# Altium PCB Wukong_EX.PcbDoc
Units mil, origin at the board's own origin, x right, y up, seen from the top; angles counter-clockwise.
Board outline 2015.75 x 1811.02 mil, 4 copper layers (Top Layer, Internal Plane 1, MidLayer2, Bottom Layer), stack 33.217 mil thick; 59 components, 65 nets, 213 pads, 28 vias.
Unrouted connection lines stored in the file: 1.
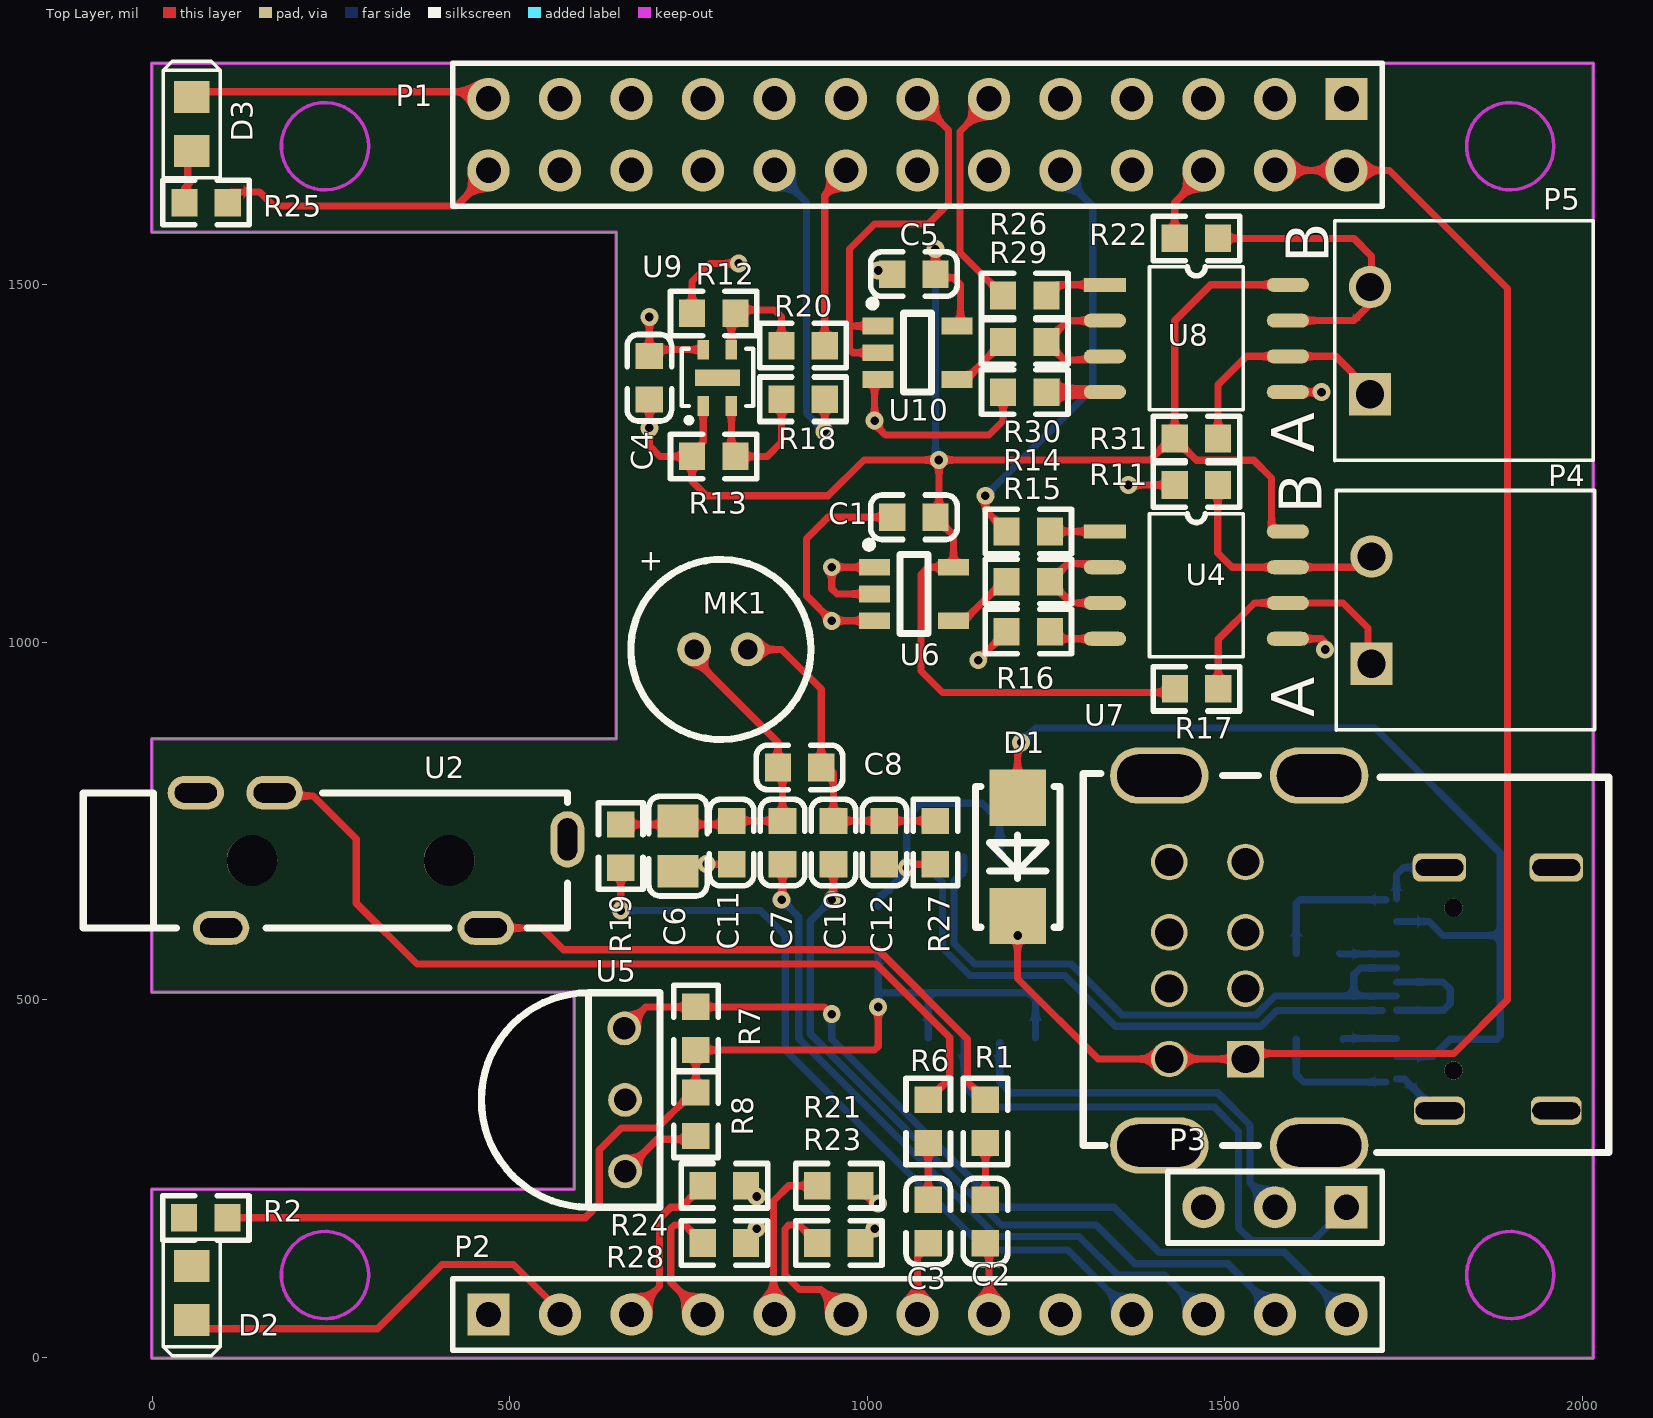
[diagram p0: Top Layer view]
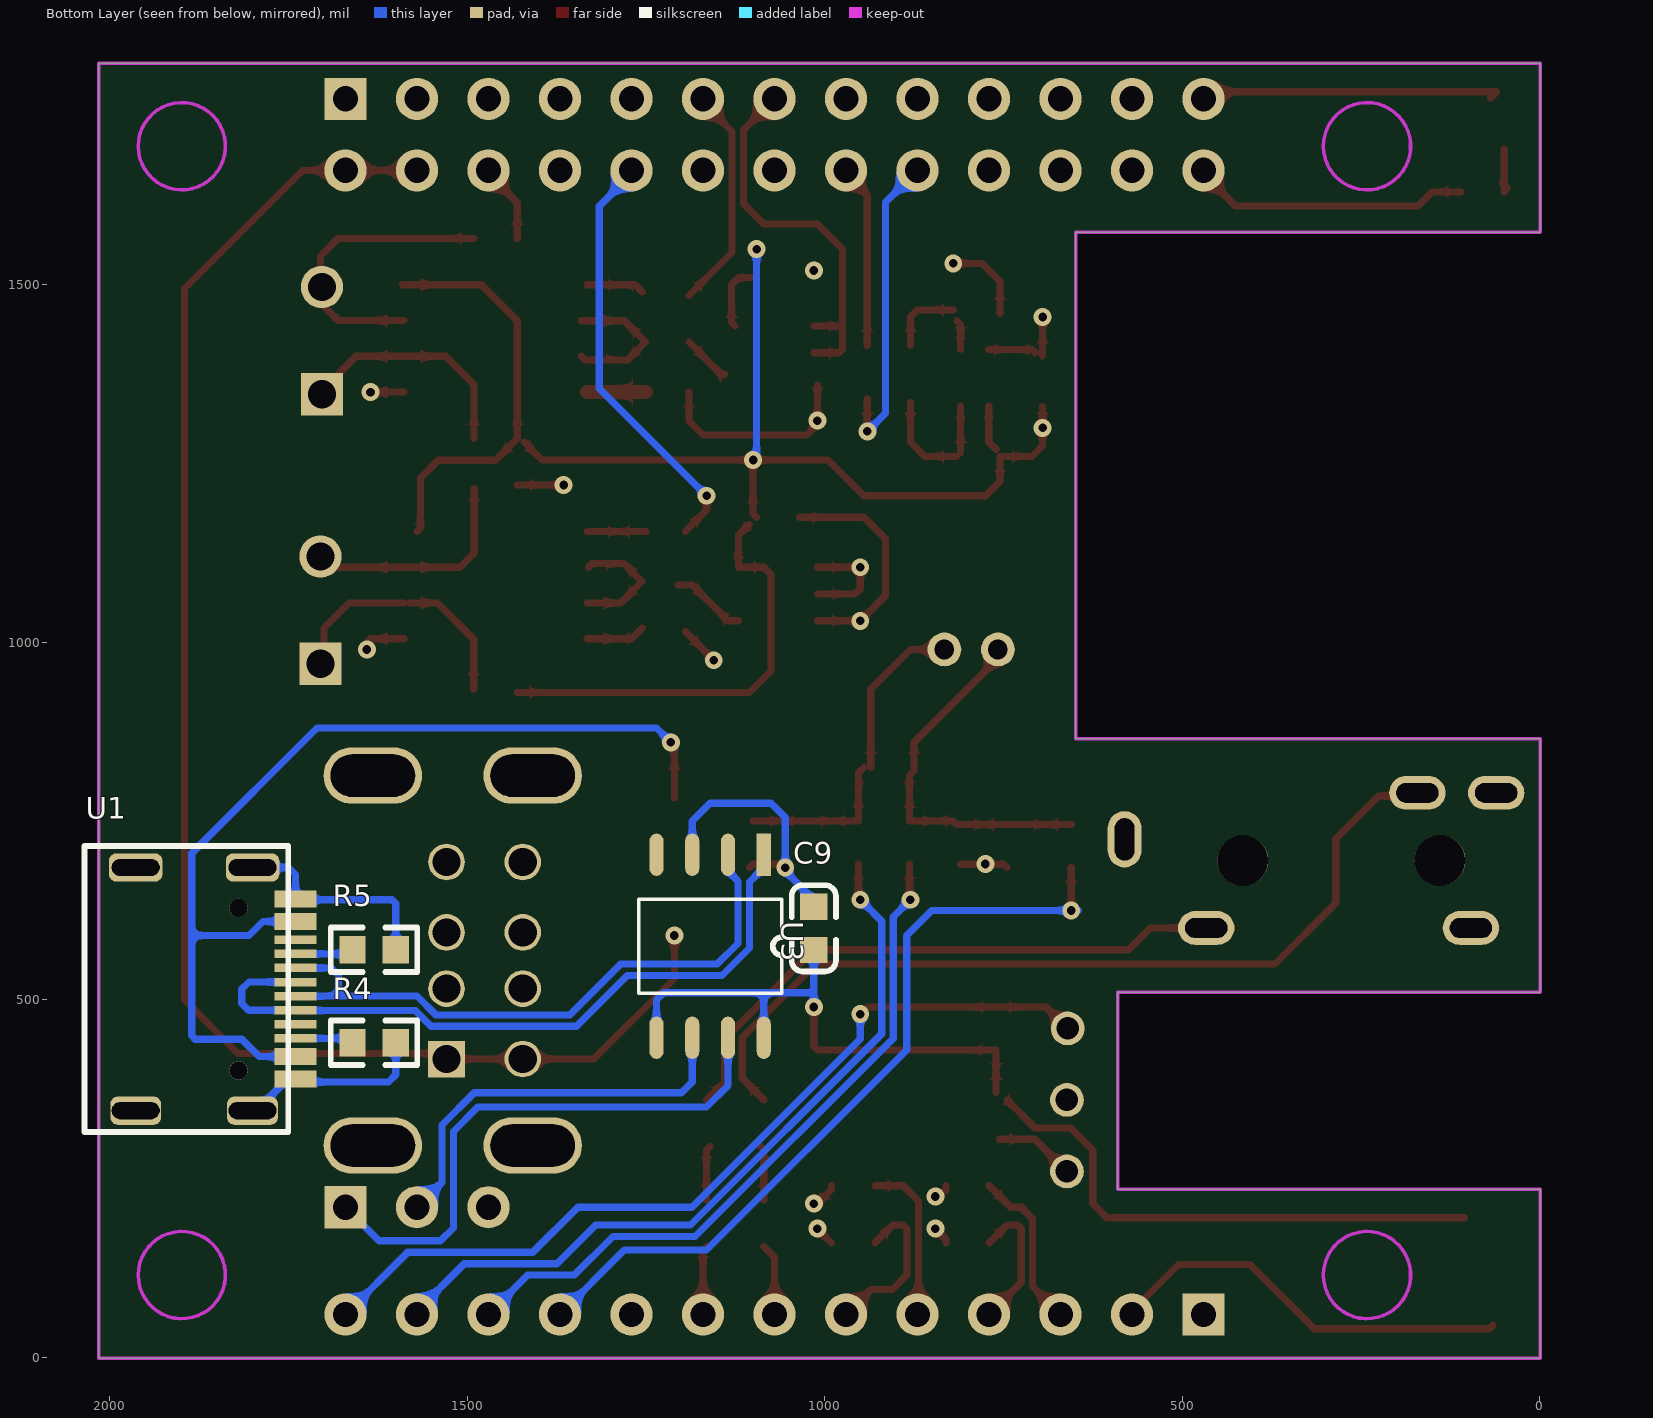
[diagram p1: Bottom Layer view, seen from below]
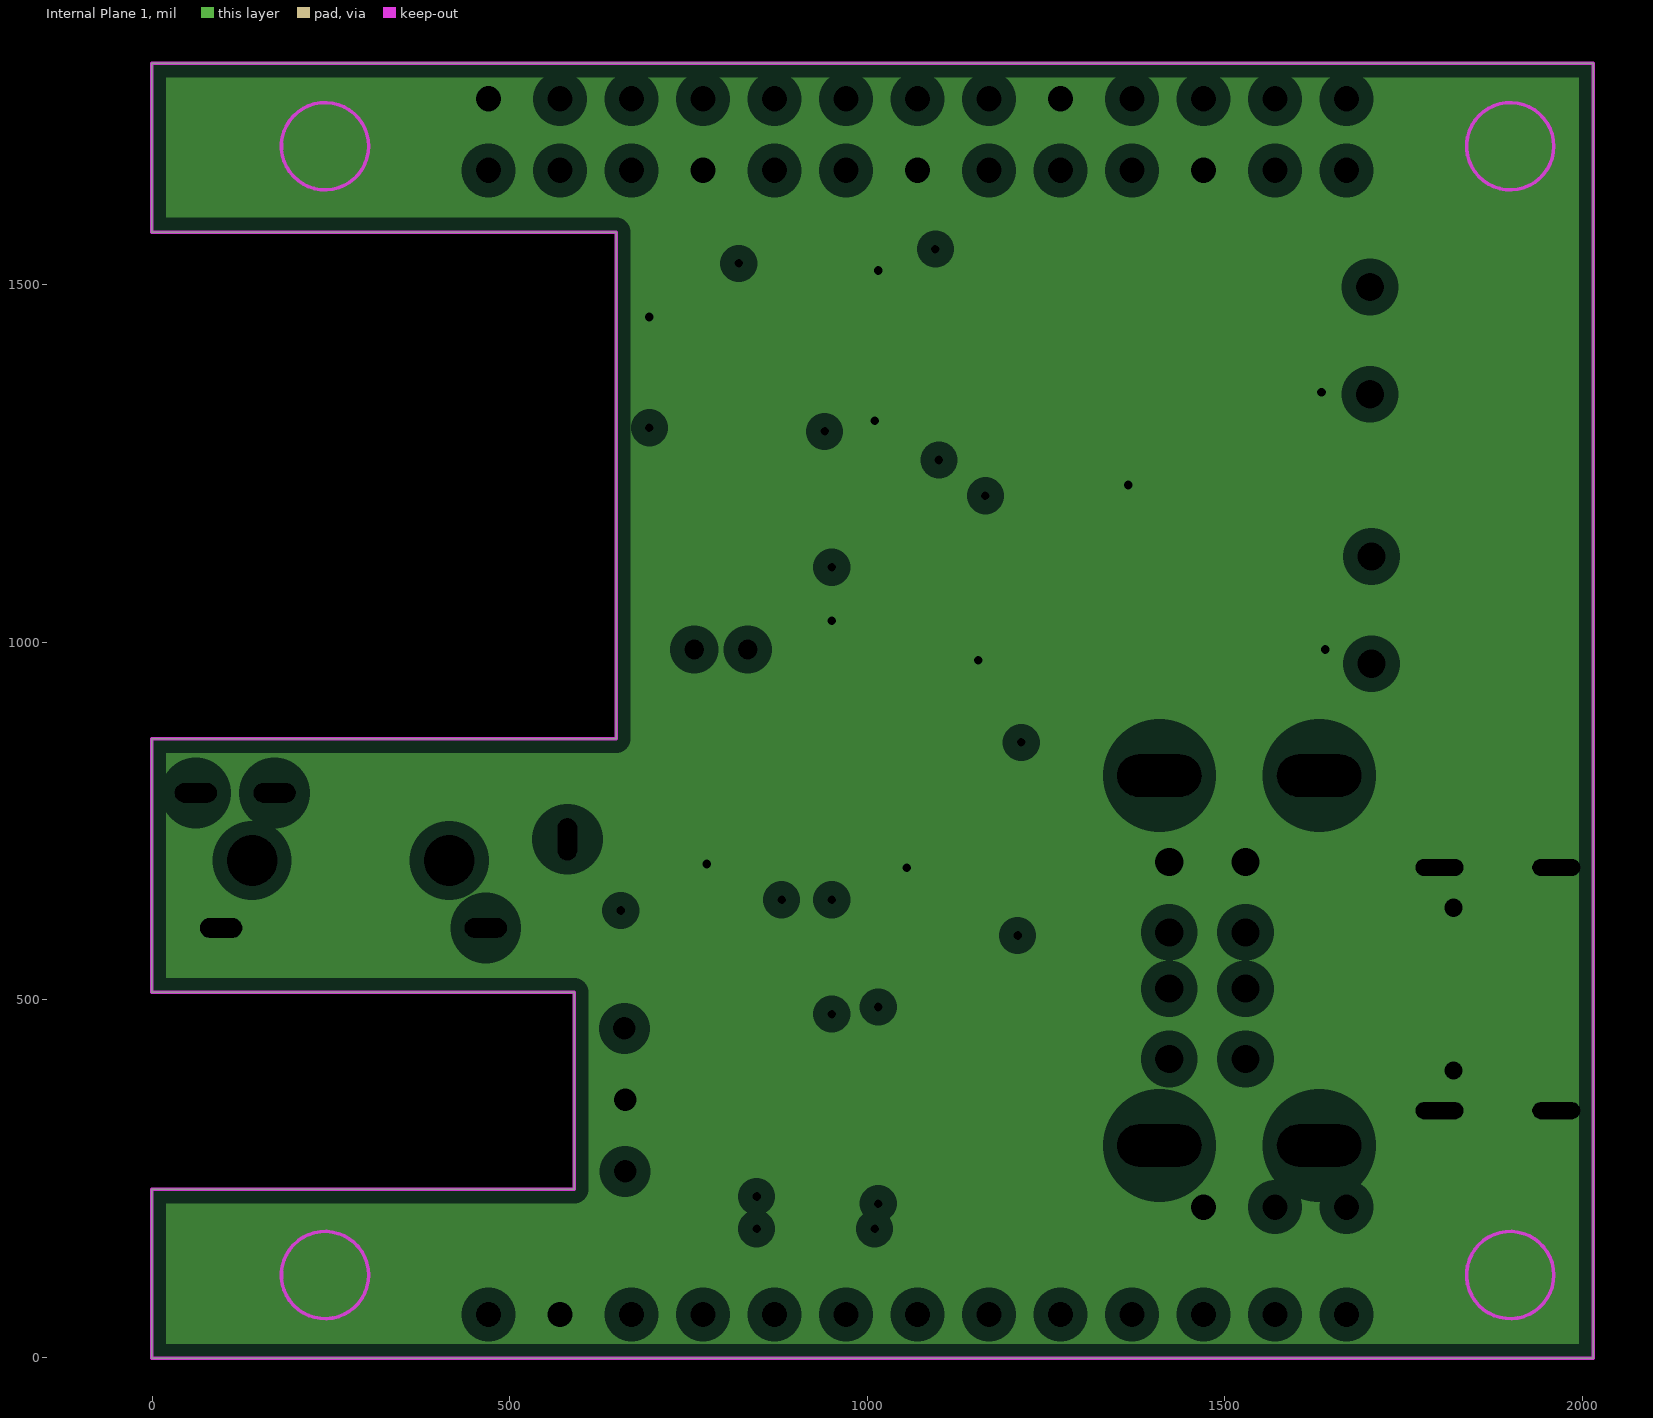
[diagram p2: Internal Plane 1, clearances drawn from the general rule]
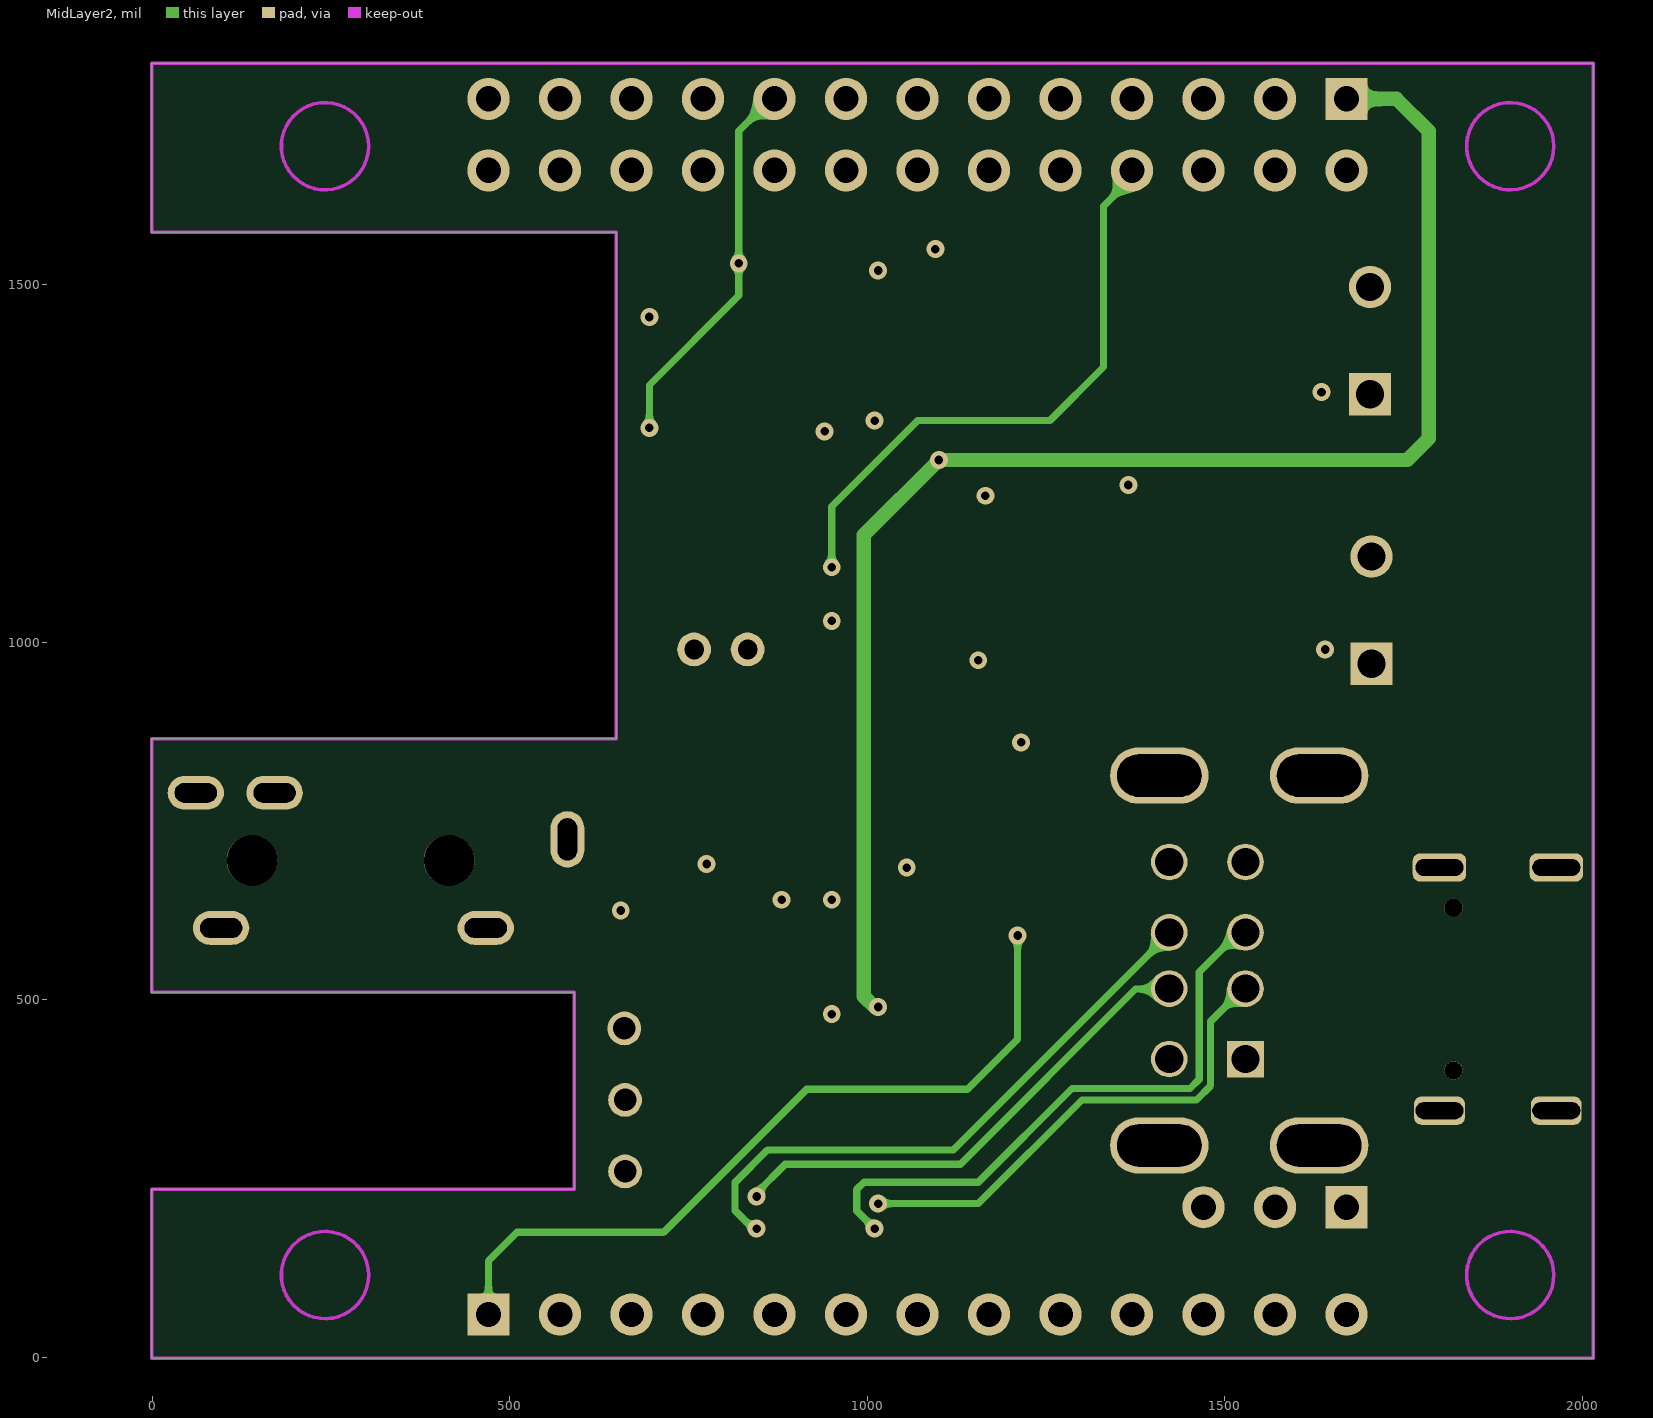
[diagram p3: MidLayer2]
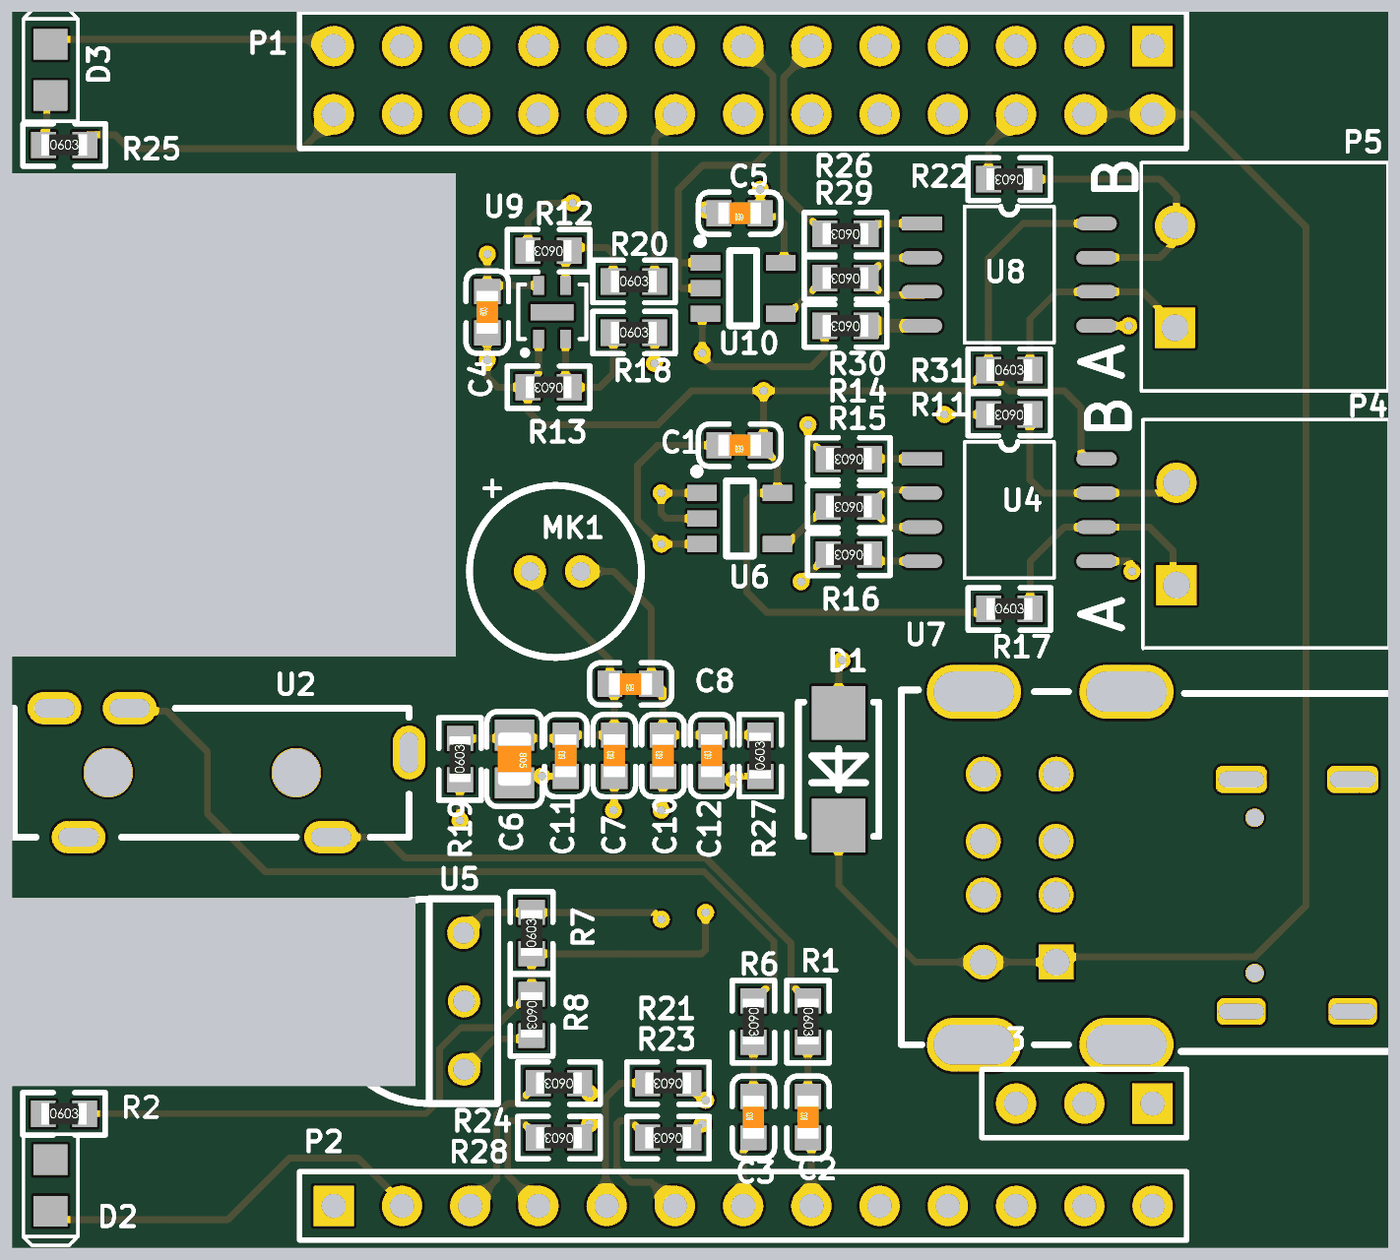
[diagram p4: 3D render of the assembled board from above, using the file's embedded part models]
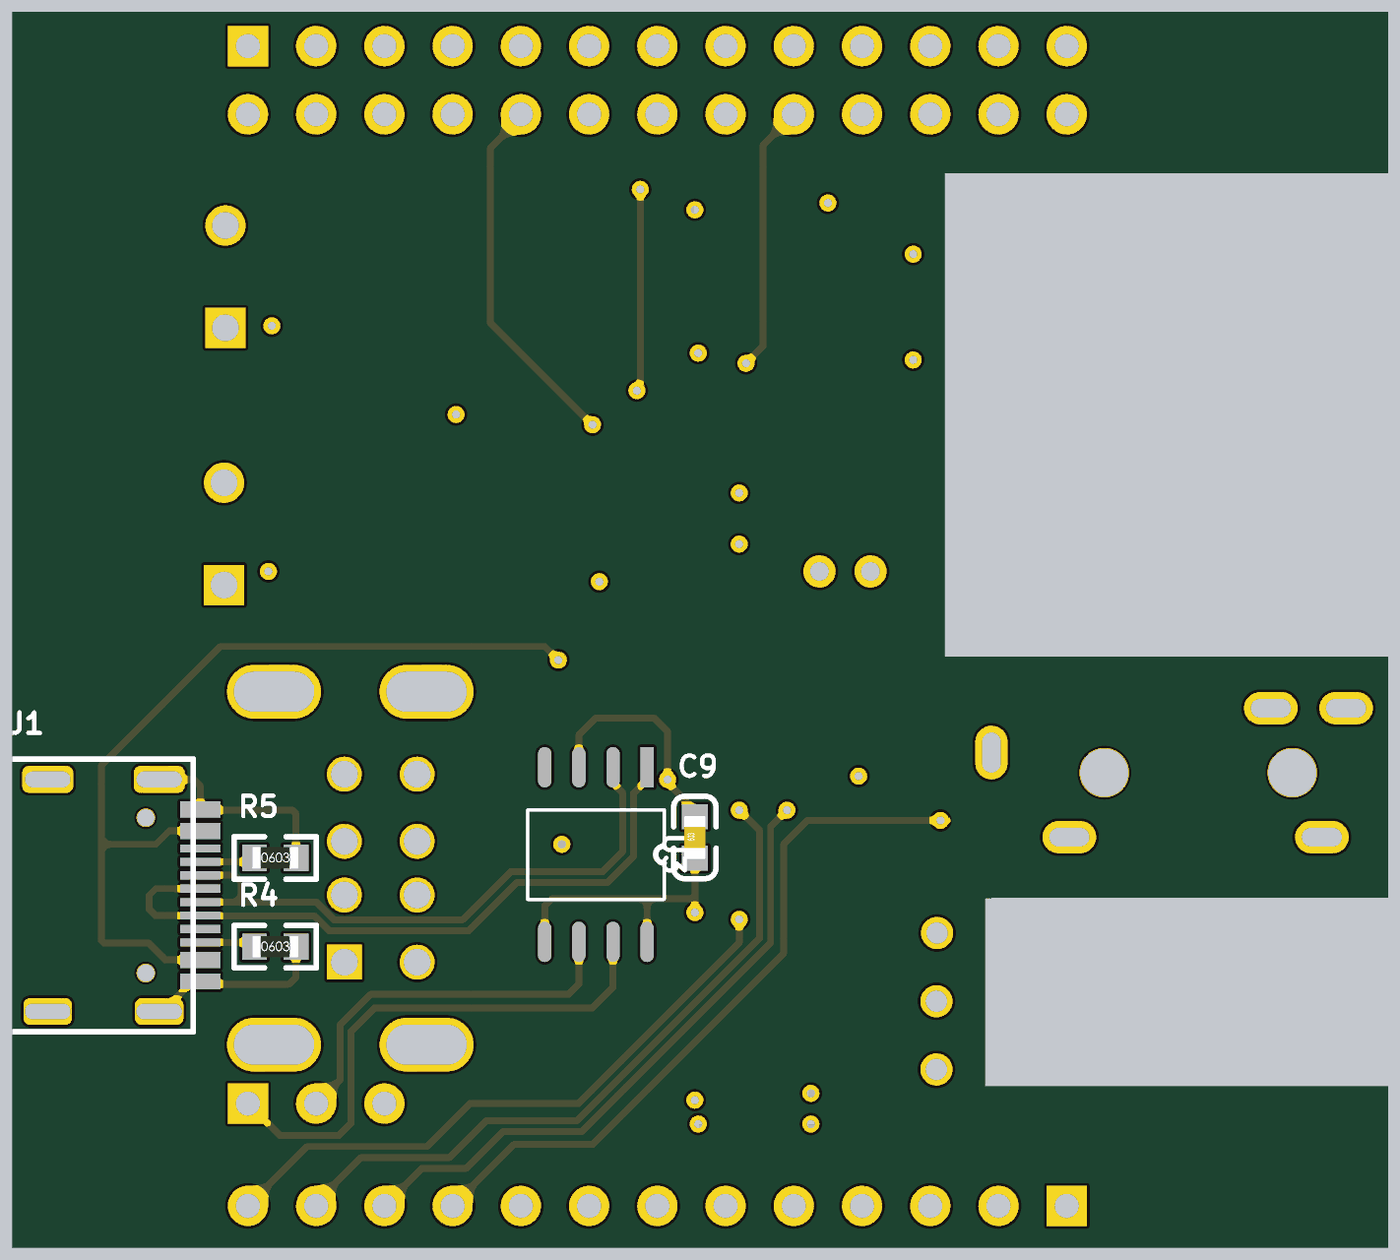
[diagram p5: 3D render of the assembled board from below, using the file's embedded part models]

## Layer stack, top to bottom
Top Solder: solder mask 0.4, Solder Resist, Dk 3.5
Top Layer: signal copper 1.4
Dielectric1: core 12.6, FR-4, Dk 4.8
Internal Plane 1: plane copper 1.417, net GND
Dielectric3: core 10, FR-4, Dk 4.2
MidLayer2: signal copper 1.4
Dielectric 4: prepreg 5, Dk 4.2
Bottom Layer: signal copper 1.4
Bottom Solder: solder mask 0.4, Solder Resist, Dk 3.5

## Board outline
-0.75,-1.01 -0.75,235.21 589.8,235.21 589.8,510.8 -0.75,510.8 -0.75,865.13 648.86,865.13 648.86,1573.79 -0.75,1573.79 -0.75,1810.01 2015,1810.01 2015,-1.01

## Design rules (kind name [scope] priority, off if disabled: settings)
Clearance [All] p1: gap=6
FabricationTestPointUsage TestPointUsage [All] p1: valid=0 allowmultiple=FALSE
FabricationTestpoint Testpoint [All] p1: side=3 testpointundercomponent=TRUE minsize=40 maxsize=100 preferedsize=60 minholesize=0 maxholesize=40 preferedholesize=32 testpointgrid=1 allowsidetop=TRUE allowsidebottom=TRUE usegrid=TRUE gridtolerance=0.01
PlaneClearance [All] p1: clearance=20
PlaneConnect [All] p1: planeconnectstyle=Relief reliefexpansion=20 reliefentries=4 reliefconductorwidth=10 reliefairgap=10
PolygonConnect [All] p1: connectstyle=Relief reliefconductorwidth=10 reliefentries=4 polygonreliefangle="90 Angle" airgapwidth=10
RoutingVias [All] p1: holewidth=28 width=50 viastyle="Through Hole" minholewidth=28 minwidth=50 maxholewidth=28 maxwidth=50
SilkToSolderMaskClearance SilkscreenOverComponentPads [IsPad] p1: minsilkscreentomaskgap=10 clearancetoexposedcopper=TRUE
SolderMaskExpansion [All] p1: expansion=4
Width [All] p1: maxlimit=50 minlimit=10 preferedwidth=10
25 further rules are at their usual default settings.

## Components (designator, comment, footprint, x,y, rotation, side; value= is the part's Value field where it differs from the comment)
C1 "CAP" C0603 1065,1175 r180 top
C2 "CAP" C0603 1165,190 r90 top
C3 "CAP" C0603 1085,190 r90 top
C4 "CAP" C0603 695,1370 r90 top
C5 "CAP" C0603 1065,1515 r180 top
C6 "CAP" C0805 735,715 r270 top
C7 "CAP" C0603 881.25,720 r90 top
C8 "CAP" C0603 905,825 r180 top
C9 "CAP" C0603 1015,600 r90 bottom
C10 "CAP" C0603 952.5,720 r90 top
C11 "CAP" C0603 810,720 r90 top
C12 "CAP" C0603 1023.75,720 r90 top
D1 "1N4007" DO-214AC 1210,700 r90 top
D2 "LED" LED_0805 55,90 r270 top
D3 "LED" LED_0805 55,1725 r90 top
MK1 "MIC" MIC 795,990 r0 top
P1 "Header 13X2" HDR2X13 1670,1760 r180 top locked
P2 "Header 13" HDR1X13 470,60 r0 top locked
P3 "Header 3" HDR1X3 1670,210 r180 top locked
P4 "WJ15EDGRC-3.81-2P6GR" WJ15EDGRC-3.81-2P6GR 2017.02,878 r90 top
P5 "WJ15EDGRC-3.81-2P6GR" WJ15EDGRC-3.81-2P6GR 2015,1255 r90 top
R1 "RES" R0603 1165,330 r270 top
R2 "RES" R0603 74.68,195 r0 top
R4 "RES" R0603 1630,440 r180 bottom
R5 "RES" R0603 1630,570 r180 bottom
R6 "RES" R0603 1085,330 r270 top
R7 "RES" R0603 760,460 r90 top
R8 "RES" R0603 760,340 r270 top
R11 "RES" R0603 1460,1220 r180 top
R12 "RES" R0603 785,1460 r180 top
R13 "RES" R0603 785,1260 r180 top
R14 "RES" R0603 1225,1155 r180 top
R15 "RES" R0603 1225,1085 r180 top
R16 "RES" R0603 1225,1015 r180 top
R17 "RES" R0603 1460.31,935 r0 top
R18 "RES" R0603 910,1340 r0 top
R19 "RES" R0603 655,715 r90 top
R20 "RES" R0603 910,1415 r0 top
R21 "RES" R0603 960,240 r180 top
R22 "RES" R0603 1460,1565 r180 top
R23 "RES" R0603 960,160 r180 top
R24 "RES" R0603 800,240 r180 top
R25 "RES" R0603 75,1615 r0 top
R26 "RES" R0603 1220,1485 r180 top
R27 "RES" R0603 1095,720 r90 top
R28 "RES" R0603 800,160 r180 top
R29 "RES" R0603 1220,1420 r180 top
R30 "RES" R0603 1220,1350 r180 top
R31 "RES" R0603 1460,1285 r0 top
U1 "USB-TypeC-16Pin" USB-TYPE-C-16PIN 2035,515 r180 bottom
U2 "PJ328A" PJ-328A -96.81,600.51 r0 top
U3 "CH330" SOIC-8 1160,575 r270 bottom
U4 "Max485" SOIC-8 1460,1080 r0 top
U5 "IRM-3638L" IRM-3638L 660,460 r270 top
U6 "SN74AHCT1G00" SOT-235 1065.12,1067.6 r0 top
U7 "USB_2_UP_W" USB_2_UP_W 2035,555 r90 top locked
U8 "Max485" SOIC-8 1460,1425 r0 top
U9 "SHT-C3" SHTC3 770.32,1330.63 r90 top
U10 "SN74AHCT1G00" SOT-235 1070,1405 r0 top

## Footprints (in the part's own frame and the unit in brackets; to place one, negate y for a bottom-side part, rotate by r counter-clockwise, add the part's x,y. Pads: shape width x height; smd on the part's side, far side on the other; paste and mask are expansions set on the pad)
C0603 [mm]
  rect 0.93x0.98 smd: 1(-0.77,0) 2(0.77,0)
  silkscreen extent -1.53,-0.79 1.54,0.79, body extent -0.8,-0.4 0.8,0.4, height 0.3
C0805 [mm]
  rect 1.16x1.47 smd: 1(-0.89,0) 2(0.89,0)
  silkscreen extent -1.77,-1.04 1.77,1.04, body extent -1,-0.62 1,0.63, height 0.77
DO-214AC [mm]
  rect 2x2 smd: 1(2.1,0) 2(-2.1,0)
  silkscreen extent -2.5,-1.5 2.5,1.5, body extent -3,-1.4 3,1.4, height 2.5
HDR1X3 [mm] "Connector; Header; 3 Position"
  rect 1.5x1.5 hole 0.9: 1(0,0)
  round 1.5 hole 0.9: 2(2.54,0) 3(5.08,0)
  silkscreen extent -1.27,-1.27 6.35,1.27
HDR1X13 [mm] "Connector; Header; 13 Position"
  rect 1.5x1.5 hole 0.9: 1(0,0)
  round 1.5 hole 0.9: 2(2.54,0) 3(5.08,0) 4(7.62,0) 5(10.16,0) 6(12.7,0) 7(15.24,0) 8(17.78,0) 9(20.32,0) 10(22.86,0) 11(25.4,0) 12(27.94,0) 13(30.48,0)
  silkscreen extent -1.27,-1.27 31.75,1.27
HDR2X13 [mm] "Connector; Header; 13x2 Position"
  rect 1.5x1.5 hole 0.9: 1(0,0)
  round 1.5 hole 0.9: 2(0,2.54) 3(2.54,0) 4(2.54,2.54) 5(5.08,0) 6(5.08,2.54) 7(7.62,0) 8(7.62,2.54) 9(10.16,0) 10(10.16,2.54) 11(12.7,0) 12(12.7,2.54) 13(15.24,0) 14(15.24,2.54) 15(17.78,0) 16(17.78,2.54) 17(20.32,0) 18(20.32,2.54) 19(22.86,0) 20(22.86,2.54) 21(25.4,0) 22(25.4,2.54) 23(27.94,0) 24(27.94,2.54) 25(30.48,0) 26(30.48,2.54)
  silkscreen extent -1.27,-1.27 31.75,3.81
IRM-3638L [mm]
  round 1.2 hole 0.8: 1(0,0) 2(2.54,0.025) 3(5.08,0.025)
  silkscreen extent -1.27,-5.08 6.35,1.27, body extent -1.46,-6.28 6.54,1.71, height 8.25
LED_0805 [mm]
  rect 1.14x1.27 smd: 1(-0.955,0) 2(0.955,0)
  silkscreen extent -1.91,-1.02 2.23,1.02, body extent -1,-0.6 1,0.6, height 0.5
MIC [mm]
  round 1.2 hole 0.7: 1(-0.95,0) 2(0.95,0)
  silkscreen extent -3.2,-3.2 3.2,3.2
PJ-328A [mm] "3.5mm耳机接口"
  round 1.8 hole 1.8: 0(6,2.4) 0(13,2.4)
  oval 2x1.2 hole 0.7 slot 1.5 at 0 deg: 3(4.9,0) 4(6.8,4.8) 6(14.3,0) 7(4,4.8)
  oval 1.2x2 hole 0.7 slot 1.5 at 90 deg: 5(17.2,3.15)
  silkscreen extent 0,0 17.2,4.8, body extent 0.04,0 17.23,4.88, height 6
R0603 [mm]
  rect 0.93x0.98 smd: 1(-0.77,0) 2(0.77,0)
  silkscreen extent -1.53,-0.79 1.54,0.79, body extent -0.85,-0.4 0.85,0.4, height 0.56
SHTC3 [mm]
  rect 0.6x1.6 smd: 0(1,-0.5)
  rect 0.7x0.4 smd: 1(0,0) 2(0,-1) 3(2,-1) 4(2,0)
  silkscreen extent -0.57,-1.78 2.03,0.76, body extent 0,-1.78 2.03,0.76, height 0.75
SOIC-8 [mm]
  rect 1.5x0.5 smd: 1(-3.25,1.905)
  oval 1.5x0.5 smd: 2(-3.25,0.635) 3(-3.25,-0.635) 4(-3.25,-1.905) 5(3.25,-1.905) 6(3.25,-0.635) 7(3.25,0.635) 8(3.25,1.905)
  silkscreen extent -1.67,-2.54 1.67,2.54, body extent -1.7,-2.54 1.68,2.57, height 1
SOT-235 [mm]
  rect 1.1x0.6 smd: 1(-1.4,0.95) 2(-1.4,0) 3(-1.4,-0.95) 4(1.4,-0.95) 5(1.4,0.95)
  silkscreen extent -1.72,-1.4 0.5,1.87, body extent -0.89,-1.55 0.89,1.55, height 2
USB-TYPE-C-16PIN [mm]
  rrect50% 1.8x1 hole 0.6 slot 1.7 at 0 deg: 0(1.819,-4.318) 0(5.969,-4.318)
  rrect50% 1.9x1 hole 0.6 slot 1.7 at 0 deg: 0(1.819,4.322) 0(5.969,4.322)
  round 0.65 hole 0.65: 0(5.469,-2.888) 0(5.469,2.892)
  rect 1.5x0.6 smd: 1(7.498,3.202) 2(7.498,2.402) 11(7.498,-2.398) 12(7.498,-3.198)
  rect 1.5x0.3 smd: 3(7.498,1.752) 4(7.498,1.252) 5(7.498,0.752) 6(7.498,0.252) 7(7.498,-0.248) 8(7.498,-0.748) 9(7.498,-1.248) 10(7.498,-1.748)
  silkscreen extent 0,-5.08 7.24,5.08, body extent 0,-5.08 7.24,5.08, height 3
USB_2_UP_W [mm] "双层USB接口,上接触式，90度弯"
  oval 2x3.5 hole 1.5 slot 3 at 90 deg: 0(-6.57,15.921) 0(-6.57,10.241) 0(6.57,15.921) 0(6.57,10.241)
  rect 1.3x1.3 hole 1: 1(-3.5,12.861)
  round 1.3 hole 1: 2(-1,12.861) 3(1,12.861) 4(3.5,12.861) 5(-3.5,15.571) 6(-1,15.571) 7(1,15.571) 8(3.5,15.571)
  silkscreen extent -6.82,-0.05 6.64,18.62, body extent -6.82,-0.05 6.64,18.62, height 15
WJ15EDGRC-3.81-2P6GR [mm]
  rect 1.5x1.5 hole 1: 1(2.337,7.925)
  round 1.5 hole 1: 2(6.147,7.925)
  silkscreen extent -0.03,0 8.49,9.18, body extent 0,-0.05 8.51,9.22, height 7

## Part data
C1 C2 C3 C4 C5 C6 C7 C8 C9 C10 C11 C12: library part 无极电容, "无极电容"
D1: library part 二极管, "二极管"
MK1: "咪头，驻极体话筒"
P1: "Header, 13-Pin, Dual row"
P2: "Header, 13-Pin"
P3: "Header, 3-Pin"
P4 P5: "3.81-2P-Green-90"
R1 R2 R4 R5 R6 R7 R8 R11 R12 R13 R14 R15 R16 R17 R18 R19 R20 R21 R22 R23 R24 R25 R26 R27 R28 R29 R30 R31: "电阻"
U2: library part PJ-328A, "3.5mm音频接口"
U3: "USB 转串口"
U4 U8: "MAX-485"
U5: "红外接收头，38KHz,2.7-5.5V"
U6 U10: "双输入与非门"
U7: library part USB*2, "双层USB接口，上接触式，90度弯"
U9: "温湿度传感器"

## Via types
v1: diameter 25, hole 12, Top Layer to Bottom Layer, 28 vias

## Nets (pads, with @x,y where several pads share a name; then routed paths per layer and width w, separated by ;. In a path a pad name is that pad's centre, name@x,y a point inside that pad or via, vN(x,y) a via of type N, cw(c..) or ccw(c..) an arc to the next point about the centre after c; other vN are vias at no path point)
DP_M: U1.5 U1.7 U3.2 | length 891.6
  Bottom Layer w10: U3.2@1135,700 1135,680 1121,666 1121,579 1150,550 1285,550 1355.96,479.04 1543.82,479.04 1570.01,505.24 1680,505.24 ; 1680,505 1680,505.24 ; U1.7 1680,505.24 ; U1.5 1689.61,544.61 1680,535 1680,505.24
DP_P: U1.6 U1.8 U3.1 | length 986.5
  Bottom Layer w10: U3.1 1085,685 1105,665 1105,572.37 1143.37,534 1276,534 1346.96,463.04 1550.45,463.04 1572.41,485 U1.8@1720,485 ; U1.8 1805.55,485.55 1815,495 1815,515 1805,525 U1.6@1740,525
GND: C1.2 C4.2 C5.2 C6.2 C9.2 C11.1 C12.1 D2.2 D3.2 P1.6 P1.9 P1.14 P1.20 P1.25 P2.2 P3.3 R4.2 R5.2 R11.2 R16.2 R22.2 R27.1 R30.2 U1.0 U1.1 U1.12 U2.3 U3.3 U4.5 U5.2 U6.3 U7.4 U7.8 U8.5 U9.4 U10.3 | length 3075.3
  Top Layer w10: D2.2@65,45 70.04,39.96 314.96,39.96 405,130 505,130 P2.2@575,60 ; D3.2@68.4,1761.63 60.03,1770 455,1770 P1.25@465,1760 ; C4.2 v1(695,1455) ; C4.2@705,1405 709.37,1409.37 U9.4 ; C6.2@745,685 749.69,689.69 C11.1 ; v1(950,1030) 915,1065 915,1145 945,1175 C1.2 ; v1@955,1030 955.2,1030.2 U6.3 ; U10.3@1010,1360 v1(1010,1310) 1010,1305 1025,1290 1170,1290 1189.68,1309.68 R30.2 ; v1@1055,689.69 1100.31,689.69 R27.1@1105,685 ; v1@1155,970 v1(1155,975) 1155,975.32 R16.2 ; v1(1365,1220) R11.2 ; R22.2 1429.68,1614.68 P1.6@1470,1655 ; U4.5 1635,1005 1640,1000 v1(1640,990) ; U8.5 v1(1635,1350)
  Bottom Layer w10: C9.2 1015,640 1055,680 v1(1055,685) 1055,755 1075,775 1160,775 1185,750 U3.3 ; R4.2@1599.68,445 R4.2 1599.68,395.32 1610,385 U1.12@1725,385 ; R5.2@1599.68,565 R5.2 1599.68,634.68 1605,640 U1.1@1725,640 ; U1.12 1750.91,389.09 1795,345 1800,345 U1.0@1805,345 ; U1.1 1739.8,675.2 1749.61,685 U1.0@1790,685
  other v1: 775,690 1015,1520
IR_RX: P2.13 R7.2 U5.1 | length 1220.9
  Top Layer w10: U5.1 690,490 940,490 v1(950,480)
  Bottom Layer w10: v1(950,480) 950,445.25 1185.25,210 1345,210 1408,147 1583,147 P2.13
LINE_OUTL: C2.1 P2.8 | length 97.1
  Top Layer w10: C2.1@1165,155 1170,150 P2.8
LINE_OUTR: C3.1 P2.7 | length 101.2
  Top Layer w10: P2.7 1070,140 C3.1@1085,155
MIC_1N: C10.1 P2.12 | length 1059
  Top Layer w10: C10.1 952.5,642.5 v1@955,640
  Bottom Layer w10: v1@945,635 920,610 920,452.63 1187.63,185 1320,185 1374,131 1504,131 1570,65 P2.12
  other v1: 950,640
MIC_1P: C7.1 P2.11 | length 985
  Top Layer w10: v1(880,640) 881.25,641.25 C7.1
  Bottom Layer w10: v1@880,645 v1(880,640) 904,616 904,446 1181,169 1296,169 1350,115 1415,115 P2.11
MIC_MBIAS: P2.10 R19.1 | length 1114.5
  Top Layer w10: R19.1 655,630 v1@660,625
  Bottom Layer w10: v1@645,625 v1(655,625) 850,625 885,590 885,430 1165,150 1280,150 P2.10
NetC2_2: C2.2 R1.2 | length 76.8
  Top Layer w10: R1.2@1160,295 1165,290 C2.2
NetC3_2: C3.2 R6.2 | length 76.8
  Top Layer w10: C3.2 1085,290 R6.2@1090,295
NetC6_1: C6.1 C7.2 C8.2 C11.2 MK1.1 R19.2 | length 513.4
  Top Layer w10: R19.2 814.68,745.32 815,745 820.32,750.32 C7.2 881.25,813.75 C8.2@875,820 ; MK1.1@760,990 760,975 874.68,860.32 C8.2
NetC8_1: C8.1 C10.2 C12.2 MK1.2 R27.2 | length 463.3
  Top Layer w10: MK1.2@830,990 MK1.2 880,990 935.31,934.69 C8.1 ; C8.1@945,825 952.5,817.5 C10.2 C12.2 1099.68,750.32 R27.2@1100,750
NetD1_1: D1.1 U1.2 U1.11 | length 1405.8
  Top Layer w10: D1.1 1210,860 v1@1215,865
  Bottom Layer w10: v1@1220,860 v1(1215,860) 1235,880 1710,880 1885,705 1885,590 ; U1.11 1790.59,420.59 1815,445 1880,445 1885,450 1885,590 ; U1.2 1785.43,609.57 1805,590 1885,590
NetD2_1: D2.1 R2.1
NetD3_1: D3.1 R25.1 | length 70.7
  Top Layer w10: 45,1635 49.37,1639.37 ; R25.1@49.37,1630 49.37,1639.37 ; D3.1@50,1690 49.37,1689.37 49.37,1639.37 ; 52.4,1642.4 49.37,1639.37
NetR1_1: R1.1 U2.6 | length 833.3
  Top Layer w10: U2.6 544.49,600.51 575,570 1015,570 1140,445 1140,385.31 R1.1
NetR4_1: R4.1 U1.10 | length 75.3
  Bottom Layer w10: R4.1@1665,445 1666.18,446.18 U1.10
NetR5_1: R5.1 U1.4 | length 80.1
  Bottom Layer w10: R5.1@1660,565 1660.71,564.29 U1.4
NetR6_1: R6.1 U2.4 | length 1237.1
  Top Layer w10: U2.4@170,785 225,785 285,725 285,635 370,550 1012.37,550 1115,447.37 1115,390.31 R6.1
NetR8_2: R8.2 U5.3 | length 112.6
  Top Layer w10: U5.3 706,305 R8.2@755,305
NetR12_1: R12.1 R20.1 U9.3 | length 146.8
  Top Layer w10: U9.3 809.69,1444.69 R12.1@815,1450 ; R12.1@820,1465 870,1465 879.69,1455.31 R20.1
NetR13_1: R13.1 R18.1 U9.2 | length 193.7
  Top Layer w10: U9.2 809.69,1265.31 R13.1@810,1265 ; R13.1 860,1260 880,1280 R18.1@880,1335
NetR14_1: R14.1 U4.1 | length 82
  Top Layer w10: R14.1@1250,1155 R14.1 U4.1
NetR15_1: R15.1 U4.2 U4.3 | length 169.5
  Top Layer w10: R15.1 1280.31,1110 1325,1110 U4.2@1330,1105 ; R15.1@1260,1080 1285,1055 U4.3
NetR15_2: R15.2 U6.4 | length 105.4
  Top Layer w10: U6.4 1135.2,1030.2 1185,1080 R15.2@1205,1080
NetR16_1: R16.1 U4.4 | length 83.3
  Top Layer w10: R16.1@1255,1020 1270,1005 U4.4
NetR21_1: R21.1 U7.2 | length 720.1
  Top Layer w10: R21.1 990.31,234.69 v1@1015,210
  MidLayer2 w10: v1(1015,215) 1155,215 1300,360 1460,360 1480,380 1480,470 U7.2@1520,510
NetR23_1: R23.1 U7.3 | length 858.4
  Top Layer w10: R23.1 1010,179.69 v1(1010,180)
  MidLayer2 w10: v1(1010,180) 985,205 985,235 995,245 1155,245 1286,376 1451,376 1464,389 1464,539 U7.3@1515,590
NetR24_1: R24.1 U7.6 | length 723.3
  Top Layer w10: R24.1 830.31,234.69 v1@845,220
  MidLayer2 w10: v1(845,225) 845,230 885,270 1130,270 1375,515 1405,515 U7.6@1415,505
NetR26_1: R26.1 U8.1 | length 81.2
  Top Layer w10: R26.1@1255,1490 1265,1500 U8.1
NetR28_1: R28.1 U7.7 | length 852.3
  Top Layer w10: R28.1 830.31,165.31 v1(845,180)
  MidLayer2 w10: v1(845,180) 840,180 815,205 815,245 860,290 1120,290 1415,585 U7.7@1420,585
NetR29_1: R29.1 U8.2 U8.3 | length 204.2
  Top Layer w10: U8.3@1340,1400 1335,1395 1275.31,1395 R29.1 1280,1449.69 1339.69,1449.69 U8.2@1340,1450
NetR29_2: R29.2 U10.4 | length 68.3
  Top Layer w10: U10.4@1140,1375 1144.68,1375 R29.2
NetR30_1: R30.1 U8.4 | length 82
  Top Layer w20: R30.1@1250,1350 R30.1 U8.4
PA7: P1.12
PA10: P1.26 R25.2 | length 386.9
  Top Layer w10: R25.2@110,1630 150,1630 170,1610 425,1610 P1.26@470,1655
PWM1: P1.7
RS485_1A: P4.1 R17.2 U4.6 | length 376.3
  Top Layer w10: R17.2 1490.63,1004.37 1541.26,1055 U4.6@1580,1055 ; U4.6 1665,1055 1700,1020 P4.1@1700,950
RS485_1B: P4.2 R11.1 U4.7 | length 322.4
  Top Layer w10: R11.1@1490,1215 1490,1125 1510,1105 U4.7 1700,1105 P4.2@1710,1115
RS485_2A: P5.1 R31.2 U8.6 | length 350.1
  Top Layer w10: R31.2 1490.32,1360.32 1530,1400 U8.6 1655,1400 1700,1355 P5.1@1700,1325
RS485_2B: P5.2 R22.1 U8.7 | length 400.4
  Top Layer w10: R22.1 1680,1565 1705,1540 P5.2@1705,1485 ; U8.7 1680,1450 P5.2@1700,1470
SPI1_CS: P1.24
SPI1_MISO: P1.21
SPI1_MOSI: P1.19
SPI1_SCLK: P1.23
TV_OUT: P2.9
TWI0_SCK: P1.5
TWI0_SDA: P1.3
TWI1_SCK: P1.18 R18.2 | length 432.1
  Top Layer w10: v1(940,1295) 940.32,1295.32 R18.2
  Bottom Layer w10: P1.18@875,1655 915,1615 915,1320 v1(940,1295)
TWI1_SDA: P1.16 R20.2 | length 245.2
  Top Layer w10: R20.2 940.32,1625.32 P1.16@965,1650
U0_RXD: P3.2 U3.6 | length 559.4
  Bottom Layer w10: U3.6@1185,440 1185,385 1200,370 1490,370 1535,325 1535,245 P3.2
U0_TXD: P3.1 U3.7 | length 786.4
  Bottom Layer w10: U3.7@1135,445 1135,380 1165,350 1485,350 1519,316 1519,181 1537,163 1623,163 1665,205 P3.1@1665,210
U1_RXD: P1.10 R14.2 | length 588.1
  Top Layer w10: v1@1165,1200 1165,1184.68 R14.2
  Bottom Layer w10: v1(1165,1205) 1315,1355 1315,1610 P1.10@1270,1655
U1_TXD: P1.8 U6.1 U6.2 | length 980.4
  Top Layer w10: U6.2 957.4,1067.6 950,1075 v1(950,1105) U6.1
  MidLayer2 w10: v1(950,1105) 950,1190 1070,1310 1255,1310 1330,1385 1330,1610 P1.8@1370,1650
U2_CTS: P1.15
U2_RTS: P1.22
U2_RXD: P1.11 R26.2 | length 304.7
  Top Layer w10: P1.11@1165,1750 1129.47,1714.47 1129.47,1545.21 R26.2
U2_TXD: P1.13 U10.1 U10.2 | length 545.1
  Top Layer w10: 975,1450 975,1550 1010,1585 1085,1585 1113.47,1613.47 1113.47,1716.53 1075,1755 P1.13@1070,1755 ; U10.2 980,1405 975,1410 975,1445 977.6,1442.4 U10.1
USB_DM2: P2.3 R24.2 | length 229.9
  Top Layer w10: P2.3 709,99 709,194 725,210 739.68,210 R24.2
USB_DM3: P2.5 R21.2 | length 229.2
  Top Layer w10: P2.5 868.5,61.5 868.5,218.5 890,240 R21.2
USB_DP2: P2.4 R28.2 | length 195.8
  Top Layer w10: R28.2 744.68,185 730,185 725,180 725,105 P2.4
USB_DP3: P2.6 R23.2 | length 230.6
  Top Layer w10: R23.2@929.68,160.32 R23.2 904.68,185 890,185 884.5,179.5 884.5,115.5 905,95 935,95 P2.6
VCC_3.3V: C1.1 C4.1 C5.1 C9.1 P1.1 P1.17 R2.2 R7.1 R8.1 R12.2 R13.2 R17.1 R31.1 U3.5 U3.8 U4.8 U6.5 U8.8 U9.1 U10.5 | length 6905
  Top Layer w10: R2.2@105,195.32 605.32,195.32 625,215 625,290 656,321 706,321 R8.1@745,360 ; C4.1@695,1330 v1(695,1300) 695,1275 710,1260 R13.2 754.68,1225.32 775,1205 945,1205 995,1255 v1(1100,1255) ; R12.2 754.68,1504.68 780,1530 v1(820,1530) ; R8.1 R7.1@760,425 ; R7.1 1009.69,429.69 1015,435 v1(1015,490) ; R13.2@760,1270 770.32,1280.32 U9.1 ; C5.1@1095,1515 v1(1095,1550) ; C1.1 1100,1179.69 v1(1100,1255) ; C5.1@1100,1510 1120,1510 1130,1500 1130,1447.28 U10.5 ; C1.1@1105,1165 1120.24,1149.76 U6.5 1085,1105 1075,1095 1075,960 1105,930 R17.1@1430,930 ; R31.1@1420,1280 1395,1255 v1(1100,1255) ; U4.8@1570,1155 1565,1160 1565,1230 1540.29,1254.71 1459.98,1254.71 R31.1 1429.69,1449.69 1480,1500 U8.8 U8.8@1590,1500
  MidLayer2 w10: v1(695,1300) 695,1360 820,1485 v1(820,1530) 820,1715 860,1755 P1.17@870,1755
  MidLayer2 w20: v1(1015,490) 1010,490 995,505 995,1150 v1(1100,1255) 1755,1255 1785,1285 1785,1715 1740,1760 P1.1
  Bottom Layer w10: v1(1015,490) 1015,515 ; C9.1@1015,565 1015,515 ; U3.8 1085,510 ; v1(1095,1550) 1095,1265 v1@1105,1255 ; U3.5 1235,500 1225,510 1085,510 ; 1015,515 1020,510 1085,510
VIN: D1.2 P1.2 P1.4 P2.1 U7.1 U7.5 | length 3300.5
  Top Layer w10: D1.2@1210,595 v1(1210,590) 1210,530 1322.8,417.2 U7.5 ; U7.5@1430,420 1432.8,417.2 U7.1 1528.66,425.09 1820.09,425.09 1895,500 1895,1495 1730,1660 P1.2 P1.4@1575,1660
  MidLayer2 w10: P2.1 470,135 510,175 715,175 915,375 1140,375 1210,445 v1(1210,590)
pads on no net: U1.3 U1.9 U2.0 U2.5 U2.7 U3.4 U7.0 U9.0

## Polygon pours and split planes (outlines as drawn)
GND on Internal Plane 1 (split plane): 1994.9,19.08 19.35,19.08 19.35,215.11 589.8,215.11 593.72,215.5 597.49,216.64 600.97,218.5 604.01,221 606.51,224.04 608.37,227.52 609.51,231.29 609.9,235.21 609.9,510.8 609.51,514.72 608.37,518.49 606.51,521.96 604.01,525.01 600.97,527.51 597.49,529.37 593.72,530.51 589.8,530.9 19.35,530.9 19.35,845.03 648.86,845.03 652.78,845.42 656.55,846.56 660.02,848.42 663.07,850.92 665.57,853.96 667.42,857.44 668.57,861.21 668.95,865.13 668.95,1573.79 668.57,1577.71 667.42,1581.48 665.57,1584.96 663.07,1588 660.02,1590.5 656.55,1592.36 652.78,1593.5 648.86,1593.89 19.35,1593.89 19.35,1789.92 1994.9,1789.92

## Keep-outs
Keep-Out Layer:
  circle w5: c241.38,1693.87 r61.02
  circle w5: c1898.86,1693.87 r61.02
  circle w5: c1898.86,115.13 r61.02
  circle w5: c241.38,115.13 r61.02
  lines w5: -0.75,-1.01 2015,-1.01 2015,1810.01 -0.75,1810.01 -0.75,1573.79 648.86,1573.79 648.86,865.13 -0.75,865.13 -0.75,510.8 589.8,510.8 589.8,235.21 -0.75,235.21 -0.75,-1.01

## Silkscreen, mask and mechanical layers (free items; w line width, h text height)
Top Overlay:
  text "B" at 1645,1530 h60 r90
  text "A" at 1625,1265 h60 r90
  text "B" at 1635,1180 h60 r90
  text "A" at 1625,895 h60 r90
